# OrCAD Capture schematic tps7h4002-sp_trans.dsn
size B; title: TPS7H4002-SP  Radiation-Hardness-Assured; rev: *; note: Datasheet: SLVSFL2    EVM User Guide: SLVUBI1; note: 3-V to 5.5-V, 3-A Synchronous Step Down Converter
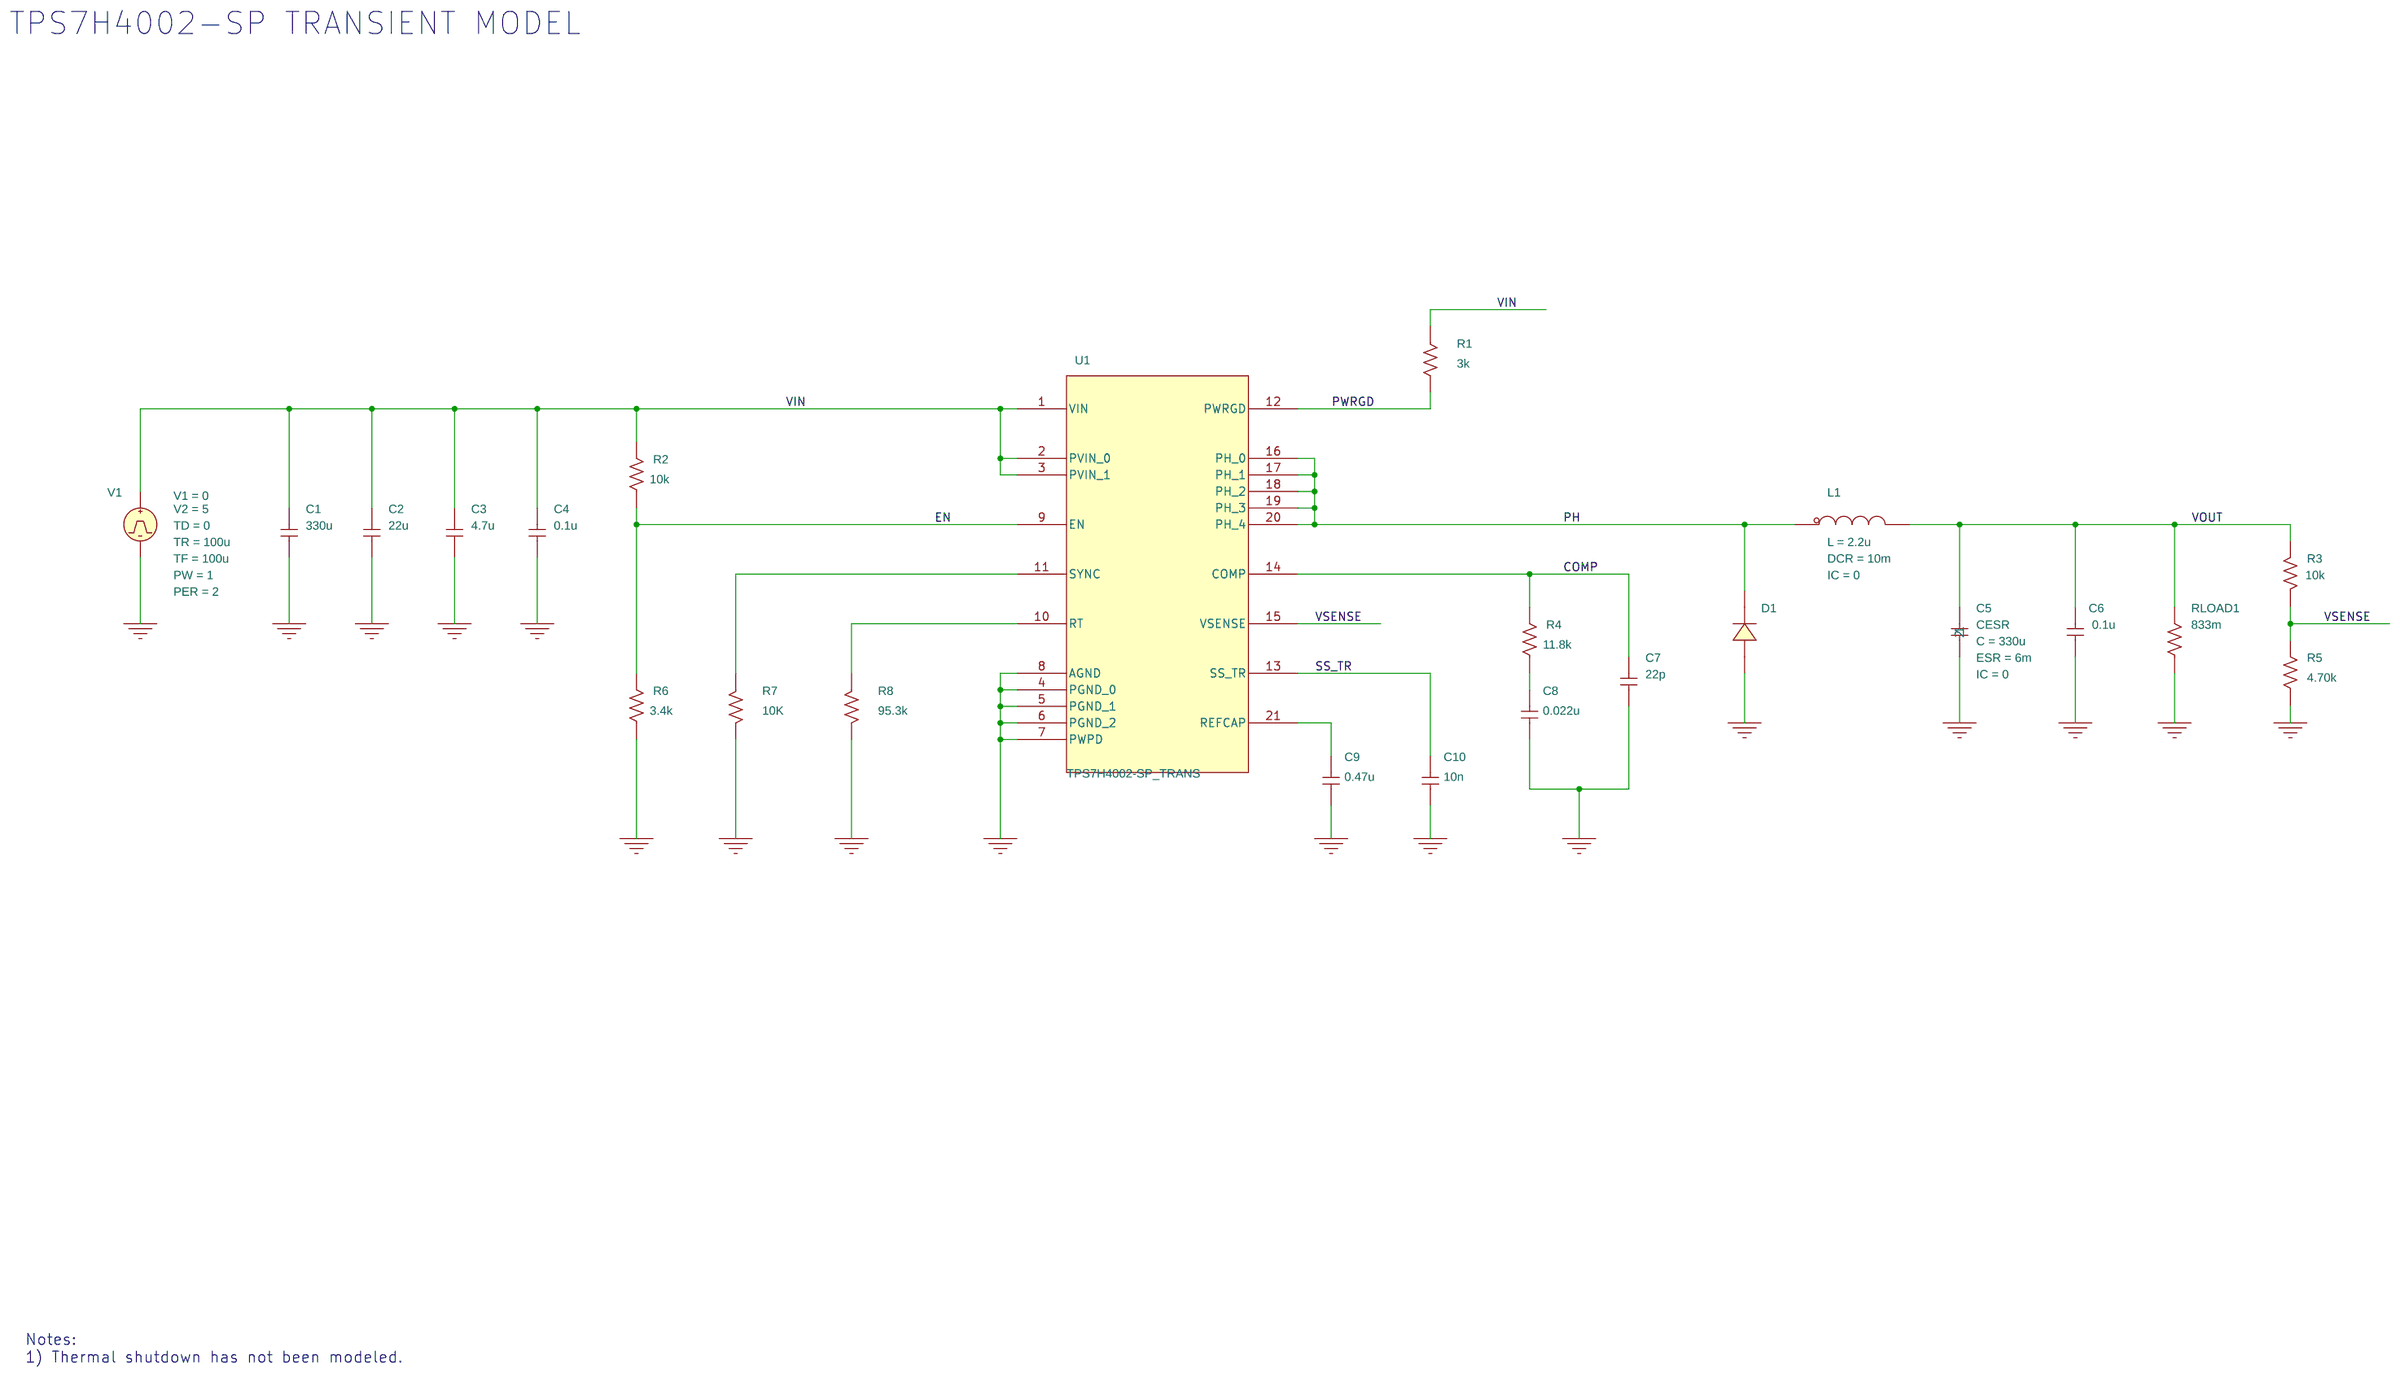
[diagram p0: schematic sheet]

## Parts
C1  330u  [RAD/CK05]
C2  22u  [RAD/CK05]
C3  4.7u  [RAD/CK05]
C4  0.1u  [RAD/CK05]
C5  CESR
C6  0.1u  [RAD/CK05]
C7  22p  [RAD/CK05]
C8  0.022u  [RAD/CK05]
C9  0.47u  [RAD/CK05]
C10  10n  [RAD/CK05]
D1  D_D1
L1  LDCR
R1  3k  [AX/RC05]
R2  10k  [AX/RC05]
R3  10k  [AX/RC05]
R4  11.8k  [AX/RC05]
R5  4.70k  [AX/RC05]
R6  3.4k  [AX/RC05]
R7  10K  [AX/RC05]
R8  95.3k  [AX/RC05]
RLOAD1  833m  [AX/RC05]
U1  TPS7H4002-SP_TRANS
V1  VPULSE

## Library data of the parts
C1-C4 C6-C10 = C
C5 = CESR: C: 330u; ESR: 6m; IC: 0; PSpiceTemplate: X^@REFDES %1 %2 @MODEL PARAMS: ?C|C=@C||C=10U| ?ESR|ESR=@ESR||ESR=2M| ?IC|IC=@IC||IC=1N| ?X|X=@X||X=1|; X: 1
D1 = D_D1
L1 = LDCR_0: DCR: 10m; IC: 0; L: 2.2u; PSpiceTemplate: X^@REFDES %IN %OUT @MODEL PARAMS:  ?L|L=@L||L=1u|  ?DCR|DCR=@DCR||DCR=0.01| ?IC|IC=@IC||IC=0|
R1-R8 RLOAD1 = R
U1 = TPS7H4002-SP_TRANS_4
V1 = VPULSE: PER: 2; PW: 1; TD: 0; TF: 100u; TR: 100u; V1: 0; V2: 5

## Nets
VIN: C1.2 C2.2 C3.2 C4.2 R1.1 R2.2 U1.1(VIN) U1.2(PVIN_0) U1.3(PVIN_1) V1.1(+)
0: C1.1 C2.1 C3.1 C4.1 C5.2 C6.1 C7.2 C8.1 C9.1 C10.1 D1.2(A) R5.1 R6.1 R7.2 R8.2 RLOAD1.1 U1.4(PGND_0) U1.5(PGND_1) U1.6(PGND_2) U1.7(PWPD) U1.8(AGND) V1.2(-)
COMP: C7.1 R4.2 U1.14(COMP)
EN: R2.1 R6.2 U1.9(EN)
PH: D1.1(C) L1.1(IN) U1.16(PH_0) U1.17(PH_1) U1.18(PH_2) U1.19(PH_3) U1.20(PH_4)
PWRGD: R1.2 U1.12(PWRGD)
SS_TR: C10.2 U1.13(SS_TR)
VOUT: C5.1 C6.2 L1.3(OUT) R3.2 RLOAD1.2
VSENSE: R3.1 R5.2 U1.15(VSENSE)
N16779967: C9.2 U1.21(REFCAP)
N16780912: C8.2 R4.1
N16782405: R8.1 U1.10(RT)
N16783007: R7.1 U1.11(SYNC)

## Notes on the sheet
- TPS7H4002-SP TRANSIENT MODEL
- Notes:
  1) Thermal shutdown has not been modeled.
